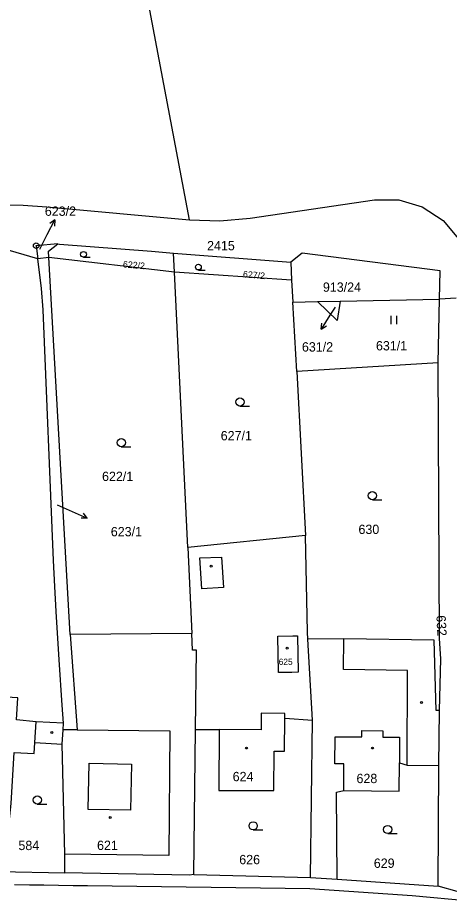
# Model space of a CAD drawing. Extents: x -504988 to -494607, y -1123820 to -1114018.
# Drawn here: x -499357.9 to -499279.1, y -1121457.6 to -1121295.8 of the extents above; entities that cross this region are included whole.
import ezdxf

# ---------------------------------------------------------------- set-up
doc = ezdxf.new("R2010")
doc.units = 0
for name, color, linetype in [('Hranice parcel', 7, 'Continuous'), ('Parcelní čísla', 7, 'Continuous'), ('Pop  PČ popisy', 7, 'Continuous'), ('Vnitřní kresba', 7, 'Continuous'), ('Značky bodu BP', 7, 'Continuous'), ('Značky budov', 7, 'Continuous'), ('Značky kultur', 7, 'Continuous')]:
    doc.layers.add(name, color=color, linetype=linetype)

msp = doc.modelspace()

# ---------------------------------------------------------------- linework, layer by layer
at = {"layer": 'Hranice parcel'}
for p, q in [((-499329.46, -1121338.65), (-499308.08, -1121340.32)), ((-499329.29, -1121342.13), (-499329.46, -1121338.65)), ((-499352.24, -1121339.48), (-499354.23, -1121339.73)), ((-499348.3, -1121408.24), (-499352.24, -1121339.48)), ((-499329.29, -1121342.13), (-499352.24, -1121339.48)), ((-499308.08, -1121340.32), (-499307.91, -1121343.62)), ((-499326.88, -1121392.33), (-499329.29, -1121342.13)), ((-499307.91, -1121343.62), (-499329.29, -1121342.13)), ((-499307.91, -1121343.62), (-499307.71, -1121347.59)), ((-499299.05, -1121347.41), (-499280.91, -1121347.04)), ((-499281.14, -1121358.66), (-499280.91, -1121347.04)), ((-499277.91, -1121346.9), (-499280.91, -1121347.04)), ((-499307.71, -1121347.59), (-499303.21, -1121347.5)), ((-499306.99, -1121360.24), (-499307.71, -1121347.59)), ((-499303.21, -1121347.5), (-499299.05, -1121347.41)), ((-499281.14, -1121358.66), (-499306.99, -1121360.24)), ((-499306.99, -1121360.24), (-499305.39, -1121390.16)), ((-499305.39, -1121390.16), (-499326.88, -1121392.33)), ((-499326.88, -1121392.33), (-499326.13, -1121408.06)), ((-499326.13, -1121408.06), (-499348.3, -1121408.24)), ((-499304.11, -1121423.84), (-499304.97, -1121409.06)), ((-499281.05, -1121432.1), (-499280.95, -1121422.06)), ((-499349.63, -1121425.58), (-499349.56, -1121424.41)), ((-499309.17, -1121423.45), (-499304.11, -1121423.84)), ((-499304.47, -1121452.54), (-499304.11, -1121423.84)), ((-499349.78, -1121428.19), (-499349.63, -1121425.58)), ((-499325.76, -1121451.97), (-499325.45, -1121425.53)), ((-499325.45, -1121425.53), (-499321.16, -1121425.55)), ((-499281.18, -1121454.13), (-499281.05, -1121432.1)), ((-499361.36, -1121451.43), (-499349.31, -1121451.65)), ((-499325.76, -1121451.97), (-499304.47, -1121452.54)), ((-499304.47, -1121452.54), (-499299.6, -1121452.85)), ((-499299.6, -1121452.85), (-499281.18, -1121454.13)), ((-499277.7, -1121455.09), (-499281.18, -1121454.13))]:
    msp.add_line(p, q, dxfattribs=at)
for points in [[(-499326.57, -1121332.59), (-499356.15, -1121176.09), (-499385.74, -1121019.59), (-499415.32, -1120863.09)], [(-499426.38, -1121294.95), (-499426.34, -1121296.55), (-499426.17, -1121297.95), (-499425.91, -1121299.28), (-499425.44, -1121300.86), (-499415.82, -1121328.48), (-499414.62, -1121330.83), (-499412.44, -1121333.04), (-499410.53, -1121334.11), (-499408.1, -1121334.77), (-499405.57, -1121334.77), (-499375.94, -1121330.72), (-499372.41, -1121330.3), (-499367.27, -1121329.91), (-499362.9, -1121329.78), (-499356.92, -1121329.9), (-499352.59, -1121330.21), (-499326.57, -1121332.59)], [(-499326.57, -1121332.59), (-499321.02, -1121332.77), (-499315.49, -1121332.29), (-499292.8, -1121328.97), (-499288.33, -1121328.98), (-499284.08, -1121330.23), (-499280.27, -1121332.72), (-499277.45, -1121336.04), (-499273.74, -1121339.27), (-499268.91, -1121340.21), (-499193.1, -1121335.01), (-499188.99, -1121335.28), (-499185.45, -1121336.48), (-499182.43, -1121338.31), (-499179.9, -1121340.84), (-499177.95, -1121344.02), (-499176.75, -1121347.92)], [(-499350.57, -1121336.99), (-499354.53, -1121337.32), (-499354.23, -1121339.73)], [(-499352.24, -1121339.48), (-499352.31, -1121338.29), (-499350.57, -1121336.99)], [(-499350.57, -1121336.99), (-499350.25, -1121337.02), (-499333.47, -1121338.33), (-499329.46, -1121338.65)], [(-499354.23, -1121339.73), (-499360.67, -1121337.84), (-499364.03, -1121338.12)], [(-499280.91, -1121347.04), (-499280.78, -1121341.89), (-499305.96, -1121338.67), (-499308.08, -1121340.32)], [(-499349.56, -1121424.41), (-499349.8, -1121421.09), (-499350.35, -1121412.84), (-499350.86, -1121404.03), (-499351.15, -1121399.47), (-499351.37, -1121394.7), (-499353.23, -1121349.03), (-499353.57, -1121345.1), (-499354.23, -1121339.73)], [(-499299.05, -1121347.41), (-499299.57, -1121350.97), (-499303.21, -1121347.5)], [(-499280.95, -1121422.06), (-499280.68, -1121412.65), (-499280.9, -1121408.95), (-499281.14, -1121358.66)], [(-499304.97, -1121409.06), (-499305.02, -1121407.81), (-499305.39, -1121390.16)], [(-499348.3, -1121408.24), (-499347.07, -1121425.6), (-499349.63, -1121425.58)], [(-499325.45, -1121425.53), (-499325.29, -1121411.09), (-499325.98, -1121411.06), (-499326.13, -1121408.06)], [(-499280.95, -1121422.06), (-499281.55, -1121422.05), (-499281.88, -1121409.26), (-499298.38, -1121409.01), (-499304.97, -1121409.06)], [(-499349.56, -1121424.41), (-499354.55, -1121424.12), (-499358.12, -1121423.8), (-499357.89, -1121419.74), (-499374.24, -1121418.79)], [(-499309.17, -1121423.45), (-499309.16, -1121422.61), (-499313.47, -1121422.59), (-499313.49, -1121425.59), (-499321.16, -1121425.55)], [(-499321.16, -1121425.55), (-499321.22, -1121436.64), (-499311.16, -1121436.69), (-499311.12, -1121429.49), (-499309.2, -1121429.5), (-499309.17, -1121423.45)], [(-499361.36, -1121451.43), (-499360.83, -1121443.79), (-499359.6, -1121443.68), (-499359.11, -1121439.02), (-499358.57, -1121429.72), (-499354.89, -1121429.93), (-499354.77, -1121427.9), (-499349.78, -1121428.19)], [(-499349.31, -1121451.65), (-499349.31, -1121448.25), (-499349.78, -1121428.19)], [(-499299.6, -1121452.85), (-499299.7, -1121436.94), (-499298.41, -1121436.69), (-499288.29, -1121436.77), (-499288.25, -1121431.59), (-499286.8, -1121432.03), (-499281.05, -1121432.1)], [(-499325.76, -1121451.97), (-499326.54, -1121452.1), (-499349.31, -1121451.65)]]:
    msp.add_lwpolyline(points, dxfattribs=at)
at = {"layer": 'Pop  PČ popisy'}
for p, q in [((-499352.51, -1121335.29), (-499351.15, -1121332.62)), ((-499351.15, -1121332.62), (-499352.05, -1121333.28)), ((-499351.15, -1121332.62), (-499351.16, -1121333.74)), ((-499353.88, -1121337.97), (-499352.51, -1121335.29)), ((-499299.99, -1121348.51), (-499300.92, -1121350)), ((-499300.92, -1121350), (-499302.51, -1121352.54)), ((-499302.51, -1121352.54), (-499302.4, -1121351.43)), ((-499302.51, -1121352.54), (-499301.55, -1121351.96)), ((-499350.69, -1121384.55), (-499347.94, -1121385.76)), ((-499347.94, -1121385.76), (-499345.2, -1121386.98)), ((-499345.2, -1121386.98), (-499345.91, -1121386.12)), ((-499345.2, -1121386.98), (-499346.32, -1121387.03))]:
    msp.add_line(p, q, dxfattribs=at)
at = {"layer": 'Vnitřní kresba'}
for p, q in [((-499324.68, -1121394.21), (-499320.72, -1121394.1)), ((-499324.28, -1121399.91), (-499324.68, -1121394.21)), ((-499320.72, -1121394.1), (-499320.37, -1121399.67)), ((-499320.37, -1121399.67), (-499324.28, -1121399.91)), ((-499310.44, -1121408.52), (-499307.67, -1121408.47)), ((-499310.29, -1121415.15), (-499310.44, -1121408.52)), ((-499307.67, -1121408.47), (-499306.84, -1121408.44)), ((-499306.84, -1121408.44), (-499306.7, -1121415.07)), ((-499298.46, -1121414.61), (-499298.38, -1121409.01)), ((-499307.89, -1121415.16), (-499310.29, -1121415.15)), ((-499306.7, -1121415.07), (-499307.89, -1121415.16)), ((-499286.78, -1121414.79), (-499298.46, -1121414.61)), ((-499286.8, -1121432.03), (-499286.78, -1121414.79)), ((-499354.77, -1121427.9), (-499354.55, -1121424.12)), ((-499347.07, -1121425.6), (-499330.12, -1121425.76)), ((-499330.12, -1121425.76), (-499330.31, -1121448.51)), ((-499295.11, -1121426.9), (-499295.1, -1121425.75)), ((-499295.1, -1121425.75), (-499291.25, -1121425.78)), ((-499291.25, -1121425.78), (-499291.26, -1121426.93)), ((-499300.02, -1121431.79), (-499299.97, -1121426.86)), ((-499299.97, -1121426.86), (-499295.11, -1121426.9)), ((-499291.26, -1121426.93), (-499288.21, -1121426.96)), ((-499288.21, -1121426.96), (-499288.25, -1121431.59)), ((-499345.03, -1121440.1), (-499344.85, -1121431.67)), ((-499344.85, -1121431.67), (-499337.11, -1121431.84)), ((-499337.11, -1121431.84), (-499337.29, -1121440.27)), ((-499298.37, -1121431.81), (-499300.02, -1121431.79)), ((-499298.41, -1121436.69), (-499298.37, -1121431.81)), ((-499337.29, -1121440.27), (-499345.03, -1121440.1)), ((-499330.31, -1121448.51), (-499349.31, -1121448.25)), ((-499345.15, -1121453.99), (-499304.58, -1121454.56)), ((-499304.58, -1121454.56), (-499285.91, -1121455.79)), ((-499285.91, -1121455.79), (-499267.3, -1121457.59))]:
    msp.add_line(p, q, dxfattribs=at)
msp.add_lwpolyline([(-499358.46, -1121453.81), (-499355.78, -1121453.85), (-499353.13, -1121453.88), (-499350.48, -1121453.92), (-499347.8, -1121453.96), (-499345.15, -1121453.99)], dxfattribs=at)
at = {"layer": 'Značky bodu BP'}
for radius in [0.5, 0.0303]:
    msp.add_circle((-499354.53, -1121337.32), radius, dxfattribs=at)
at = {"layer": 'Značky budov'}
for centre in [(-499322.58, -1121395.75), (-499308.72, -1121410.69), (-499284.19, -1121420.64), (-499351.66, -1121426.09), (-499316.16, -1121428.92), (-499293.17, -1121428.92), (-499341, -1121441.59)]:
    msp.add_circle(centre, 0.175, dxfattribs=at)
at = {"layer": 'Značky kultur'}
for p, q in [((-499345.9, -1121339.42), (-499344.67, -1121339.42)), ((-499324.93, -1121341.75), (-499323.7, -1121341.75)), ((-499289.73, -1121351.62), (-499289.73, -1121350.12)), ((-499288.73, -1121351.62), (-499288.73, -1121350.12)), ((-499317.34, -1121366.56), (-499315.59, -1121366.56)), ((-499339, -1121373.98), (-499337.25, -1121373.98)), ((-499293.17, -1121383.64), (-499291.42, -1121383.64)), ((-499354.33, -1121439.14), (-499352.58, -1121439.14)), ((-499314.93, -1121443.86), (-499313.18, -1121443.86)), ((-499290.37, -1121444.52), (-499288.62, -1121444.52))]:
    msp.add_line(p, q, dxfattribs=at)
for centre, radius in [((-499345.9, -1121338.89), 0.525), ((-499324.93, -1121341.22), 0.525), ((-499317.34, -1121365.81), 0.75), ((-499339, -1121373.23), 0.75), ((-499293.17, -1121382.89), 0.75), ((-499354.33, -1121438.39), 0.75), ((-499314.93, -1121443.11), 0.75), ((-499290.37, -1121443.77), 0.75)]:
    msp.add_circle(centre, radius, dxfattribs=at)

# ---------------------------------------------------------------- texts
at = {"layer": 'Parcelní čísla'}
for s, height, p in [('623/2', 1.7, (-499352.95, -1121331.87)), ('2415', 1.7, (-499323.34, -1121338.16)), ('913/24', 1.7, (-499302.2, -1121345.72)), ('631/2', 1.7, (-499306.03, -1121356.62)), ('631/1', 1.7, (-499292.52, -1121356.41)), ('627/1', 1.7, (-499320.85, -1121372.81)), ('622/1', 1.7, (-499342.51, -1121380.23)), ('623/1', 1.7, (-499340.91, -1121390.31)), ('630', 1.7, (-499295.71, -1121389.89)), ('625', 1.139, (-499310.27, -1121413.76)), ('624', 1.7, (-499318.67, -1121434.97)), ('628', 1.7, (-499296.07, -1121435.32)), ('584', 1.7, (-499357.77, -1121447.53)), ('621', 1.7, (-499343.42, -1121447.51)), ('626', 1.7, (-499317.47, -1121450.11)), ('629', 1.7, (-499292.91, -1121450.77))]:
    msp.add_text(s, height=height, dxfattribs=at).set_placement(p)
for s, height, rotation, p in [('622/2', 1.2, 355, (-499338.74, -1121341.27)), ('627/2', 1.2, 355, (-499316.83, -1121343.08)), ('632', 1.7, 273, (-499281.5, -1121404.75))]:
    msp.add_text(s, height=height, rotation=rotation, dxfattribs=at).set_placement(p)

doc.saveas('drawing.dxf')
